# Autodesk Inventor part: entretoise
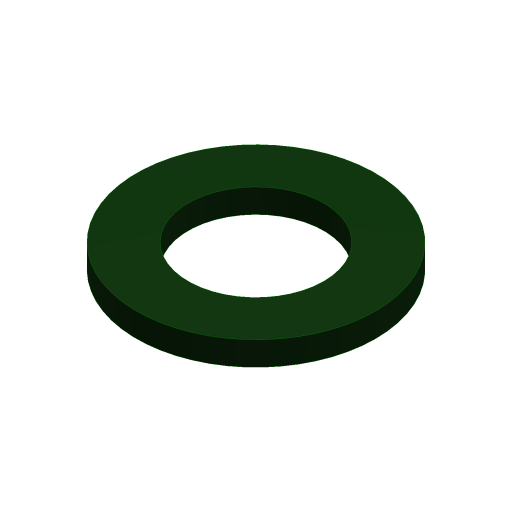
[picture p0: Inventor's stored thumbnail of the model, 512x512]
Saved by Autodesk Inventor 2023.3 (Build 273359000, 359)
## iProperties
Created: 2009-05
Part Number: entretoise
Material: Générique
Document SubType Name: Modeling
Designer: TJ
Density: 1 g/cm^3
Appearance: Par défaut
Sending System: SolidWorks 2008
Last Author: Roger
Last Saved: 2011-02-17
Author: TJ
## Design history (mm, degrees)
node "Extrusion1"
node "Solide1"
